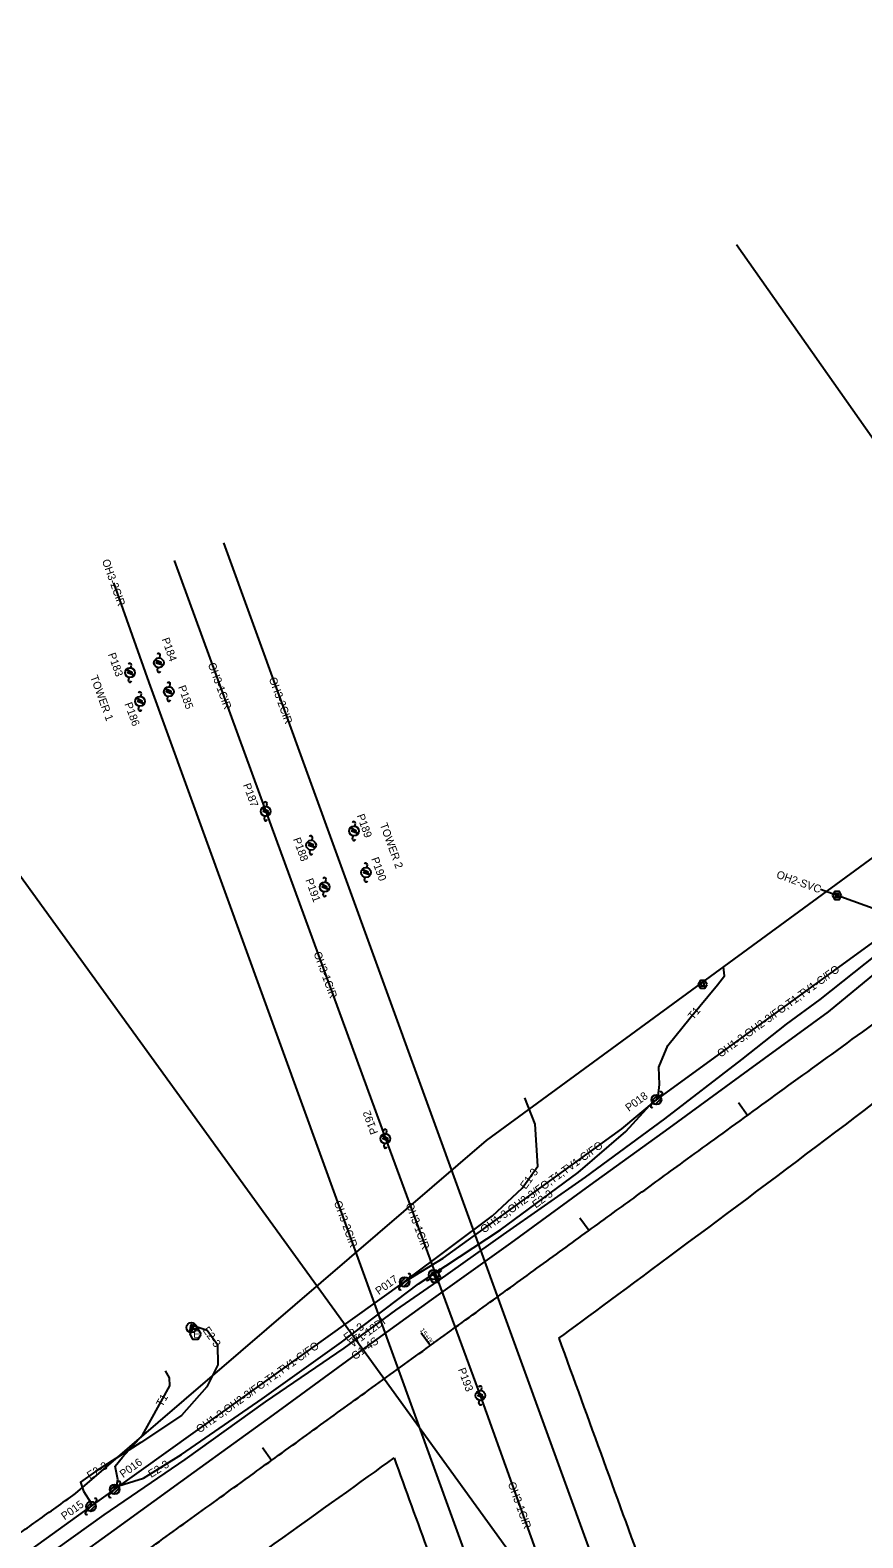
# Model space of a CAD drawing. Extents: x 1991878 to 2008544, y 770238 to 1141211.
# Drawn here: x 2004125 to 2004550, y 1139018 to 1139787 of the extents above; entities that cross this region are included whole.
import ezdxf

# ---------------------------------------------------------------- set-up
doc = ezdxf.new("R2010")
doc.units = 0
for name, color, linetype in [('RD_EX_SU_Elec', 7, 'Continuous'), ('RD_EX_SU_Gas', 7, 'Continuous'), ('RD_EX_SU_H2O', 7, 'Continuous'), ('RD_EX_SU_Ovhd', 7, 'Continuous'), ('RD_EX_SU_Pole', 7, 'Continuous'), ('RD_EX_SU_Sewer', 7, 'Continuous'), ('RD_EX_SU_SwpLmt', 7, 'Continuous'), ('RD_EX_SU_Telecom', 7, 'Continuous'), ('RD_EX_SU_TX_Elec', 7, 'Continuous'), ('RD_EX_SU_TX_Gas', 7, 'Continuous'), ('RD_EX_SU_TX_H2O', 7, 'Continuous'), ('RD_EX_SU_TX_Ovhd', 7, 'Continuous'), ('RD_EX_SU_TX_Pole', 7, 'Continuous'), ('RD_EX_SU_TX_Telecom', 7, 'Continuous'), ('RD_HC_Cl', 7, 'Continuous')]:
    doc.layers.add(name, color=color, linetype=linetype)

msp = doc.modelspace()

# ---------------------------------------------------------------- linework, layer by layer
at = {"layer": 'RD_EX_SU_Elec'}
for points in [[(2004168.09, 1139042.52), (2004168.01, 1139043.57), (2004182.88, 1139048.25), (2004202.25, 1139060.36), (2004243.35, 1139088.77), (2004283.94, 1139117.69), (2004323.11, 1139147.44), (2004365.07, 1139174.96), (2004404.63, 1139204.33), (2004429.06, 1139225.25), (2004443.17, 1139240.65), (2004444.61, 1139241.4)], [(2004316.12, 1139148.39), (2004317.11, 1139149.38), (2004360.95, 1139182.08), (2004376.07, 1139196.27), (2004384.08, 1139207.41), (2004382.8, 1139228.99), (2004377.45, 1139242.32)], [(2004208.14, 1139126.24), (2004215.41, 1139123.84), (2004220.67, 1139116.52), (2004220.86, 1139106.12), (2004215.25, 1139094.87), (2004202.23, 1139080.19), (2004181.54, 1139066.49), (2004158.37, 1139051.7), (2004150.66, 1139046.27), (2004152.27, 1139041.61), (2004156.08, 1139035.53), (2004156.05, 1139033.8)]]:
    msp.add_lwpolyline(points, dxfattribs=at)
for points in [[(2004208.71, 1139127.16), (2004207.7, 1139123.71), (2004207.2, 1139125.58), (2004206.44, 1139122.75), (2004207.13, 1139126.66), (2004207.69, 1139124.72)], [(2004212.25, 1139121.75), (2004210.81, 1139124.25), (2004207.92, 1139124.25), (2004206.48, 1139121.75), (2004207.92, 1139119.25), (2004210.81, 1139119.25)]]:
    msp.add_lwpolyline(points, close=True, dxfattribs=at)
msp.add_circle((2004207.32, 1139125.1), 2.55, dxfattribs=at)
at = {"layer": 'RD_EX_SU_Gas'}
msp.add_lwpolyline([(2004127.39, 1138992.43), (2004167.83, 1139021.75), (2004208.7, 1139051.33), (2004249.23, 1139080.61), (2004289.2, 1139109.77), (2004329.8, 1139139.24), (2004370.29, 1139168.18), (2004410.8, 1139197.77), (2004451.13, 1139226.8), (2004491.65, 1139256.41), (2004532.34, 1139286.17), (2004559.51, 1139308.55), (2004570.45, 1139319.96), (2004589.25, 1139345.84), (2004598.18, 1139366.3), (2004605.75, 1139385.94), (2004607.89, 1139395.38), (2004612.64, 1139396.79), (2004640.85, 1139410.39), (2004653.01, 1139417.54), (2004650.63, 1139421.79), (2004642.64, 1139434.89), (2004626.13, 1139463.52)], dxfattribs=at)
at = {"layer": 'RD_EX_SU_H2O'}
for p, q in [((2004334.21, 1139155.06), (2004332.65, 1139153.95)), ((2004334.94, 1139154.04), (2004334.21, 1139155.06)), ((2004328.65, 1139151.09), (2004327.03, 1139149.93)), ((2004327.03, 1139149.93), (2004327.77, 1139148.91)), ((2004327.77, 1139148.91), (2004329.42, 1139150.09)), ((2004331.81, 1139149.71), (2004332.76, 1139148.38)), ((2004332.76, 1139148.38), (2004333.79, 1139149.11)), ((2004333.79, 1139149.11), (2004332.86, 1139150.42)), ((2004333.35, 1139152.9), (2004334.94, 1139154.04))]:
    msp.add_line(p, q, dxfattribs=at)
for points in [[(2004122.45, 1139000.61), (2004162.73, 1139029.52), (2004204.05, 1139057.78), (2004245.07, 1139087.18), (2004285.23, 1139114.51), (2004311.58, 1139134.01), (2004333.1, 1139148.87), (2004366.63, 1139172.54), (2004408.38, 1139201.91), (2004448.87, 1139231.66), (2004488.17, 1139261.92), (2004511.05, 1139279.96), (2004528.13, 1139292.48), (2004557.12, 1139315.44), (2004575.83, 1139329.69), (2004595.34, 1139346.68), (2004617.3, 1139361.37), (2004649.17, 1139383.17), (2004663.69, 1139393.7), (2004675.95, 1139402.09), (2004682.78, 1139406.85), (2004687.52, 1139410.39), (2004690.03, 1139412.66)], [(2004330.96, 1139152.08), (2004331.38, 1139151.22), (2004332.8, 1139149.35), (2004333.12, 1139148.89)]]:
    msp.add_lwpolyline(points, dxfattribs=at)
msp.add_lwpolyline([(2004334.63, 1139150.7), (2004333.19, 1139153.2), (2004330.3, 1139153.2), (2004328.86, 1139150.7), (2004330.3, 1139148.2), (2004333.19, 1139148.2)], close=True, dxfattribs=at)
for radius in [2.52, 0.315]:
    msp.add_circle((2004330.96, 1139152.08), radius, dxfattribs=at)
for start, end in [(203.23728, 232.2136), (289.79782, 318.76505), (18.89099, 47.86731)]:
    msp.add_arc((2004330.96, 1139152.08), 2.52, start, end, dxfattribs=at)
at = {"layer": 'RD_EX_SU_Ovhd'}
for p, q in [((2004223.65, 1139525.67), (2004282.2, 1139364.47)), ((2004198.44, 1139516.51), (2004245.22, 1139388.55)), ((2004185.77, 1139454.37), (2004167.69, 1139505.27)), ((2004386.44, 1138901.38), (2004185.77, 1139454.37)), ((2004245.22, 1139388.55), (2004306.3, 1139221.53)), ((2004282.2, 1139364.47), (2004545.93, 1138638.38)), ((2004528.25, 1139348.79), (2004571.07, 1139333.35)), ((2004444.61, 1139241.4), (2004571.07, 1139333.35)), ((2004306.3, 1139221.53), (2004354.72, 1139090.45)), ((2004168.09, 1139042.52), (2004316.12, 1139148.39)), ((2004354.72, 1139090.45), (2004394.96, 1138978.21)), ((2004156.05, 1139033.8), (2004168.09, 1139042.52)), ((2004026.75, 1138941.13), (2004156.05, 1139033.8))]:
    msp.add_line(p, q, dxfattribs=at)
msp.add_lwpolyline([(2004316.12, 1139148.39), (2004335.77, 1139160.46), (2004427, 1139226.5), (2004444.61, 1139241.4)], dxfattribs=at)
at = {"layer": 'RD_EX_SU_Pole'}
for p, q in [((2004176.4, 1139461.77), (2004176.67, 1139463.25)), ((2004191.13, 1139466.83), (2004191.4, 1139468.3)), ((2004175.24, 1139455.38), (2004175.51, 1139456.85)), ((2004189.97, 1139460.43), (2004190.24, 1139461.91)), ((2004181.49, 1139447.13), (2004181.76, 1139448.61)), ((2004196.23, 1139452.09), (2004196.5, 1139453.57)), ((2004180.33, 1139440.73), (2004180.6, 1139442.21)), ((2004195.07, 1139445.7), (2004195.34, 1139447.17)), ((2004244.51, 1139384.62), (2004244.78, 1139386.09)), ((2004245.67, 1139391.01), (2004245.94, 1139392.49)), ((2004290.69, 1139380.96), (2004290.96, 1139382.43)), ((2004268.84, 1139373.77), (2004269.11, 1139375.25)), ((2004289.53, 1139374.56), (2004289.8, 1139376.04)), ((2004267.68, 1139367.38), (2004267.95, 1139368.85)), ((2004296.83, 1139359.81), (2004297.09, 1139361.28)), ((2004274.55, 1139346.03), (2004274.82, 1139347.51)), ((2004275.71, 1139352.43), (2004275.98, 1139353.91)), ((2004295.66, 1139353.41), (2004295.93, 1139354.89)), ((2004442.19, 1139240.76), (2004445.25, 1139243.82)), ((2004442.84, 1139239.64), (2004446.37, 1139243.17)), ((2004443.96, 1139238.99), (2004447.02, 1139242.05)), ((2004446.37, 1139243.17), (2004447.43, 1139244.23)), ((2004441.78, 1139238.58), (2004442.84, 1139239.64)), ((2004306.74, 1139223.99), (2004307.01, 1139225.46)), ((2004305.58, 1139217.59), (2004305.85, 1139219.07)), ((2004313.7, 1139147.74), (2004316.76, 1139150.8)), ((2004314.35, 1139146.62), (2004317.88, 1139150.15)), ((2004315.47, 1139145.97), (2004318.53, 1139149.03)), ((2004317.88, 1139150.15), (2004318.94, 1139151.21)), ((2004313.29, 1139145.56), (2004314.35, 1139146.62)), ((2004355.16, 1139092.91), (2004355.43, 1139094.39)), ((2004354, 1139086.52), (2004354.27, 1139087.99)), ((2004165.27, 1139039.69), (2004166.33, 1139040.75)), ((2004165.68, 1139041.87), (2004168.74, 1139044.93)), ((2004166.33, 1139040.75), (2004169.86, 1139044.29)), ((2004167.45, 1139040.1), (2004170.51, 1139043.17)), ((2004169.86, 1139044.29), (2004170.92, 1139045.35)), ((2004153.22, 1139030.97), (2004154.28, 1139032.03)), ((2004153.63, 1139033.15), (2004156.69, 1139036.21)), ((2004154.28, 1139032.03), (2004157.81, 1139035.57)), ((2004155.4, 1139031.38), (2004158.46, 1139034.44)), ((2004157.81, 1139035.57), (2004158.87, 1139036.63))]:
    msp.add_line(p, q, dxfattribs=at)
for points in [[(2004189.22, 1139465.79), (2004191.04, 1139464.61), (2004189.39, 1139464.44), (2004192.46, 1139463.3), (2004192.46, 1139463.3), (2004190.28, 1139464.34), (2004191.87, 1139464.47)], [(2004174.49, 1139460.74), (2004176.31, 1139459.55), (2004174.66, 1139459.39), (2004177.73, 1139458.25), (2004177.73, 1139458.25), (2004175.55, 1139459.29), (2004177.14, 1139459.41)], [(2004194.32, 1139451.06), (2004196.14, 1139449.88), (2004194.49, 1139449.71), (2004197.56, 1139448.57), (2004197.56, 1139448.57), (2004195.38, 1139449.61), (2004196.97, 1139449.74)], [(2004179.58, 1139446.1), (2004181.4, 1139444.91), (2004179.75, 1139444.74), (2004182.82, 1139443.6), (2004182.82, 1139443.6), (2004180.64, 1139444.64), (2004182.23, 1139444.77)], [(2004243.76, 1139389.98), (2004245.58, 1139388.79), (2004243.93, 1139388.63), (2004247, 1139387.49), (2004247, 1139387.49), (2004244.82, 1139388.53), (2004246.41, 1139388.66)], [(2004288.78, 1139379.92), (2004290.6, 1139378.74), (2004288.95, 1139378.57), (2004292.02, 1139377.43), (2004292.02, 1139377.43), (2004289.84, 1139378.47), (2004291.43, 1139378.6)], [(2004266.93, 1139372.74), (2004268.75, 1139371.55), (2004267.1, 1139371.38), (2004270.17, 1139370.24), (2004270.17, 1139370.24), (2004267.99, 1139371.29), (2004269.58, 1139371.41)], [(2004294.91, 1139358.78), (2004296.74, 1139357.59), (2004295.08, 1139357.42), (2004298.15, 1139356.28), (2004298.15, 1139356.28), (2004295.97, 1139357.32), (2004297.56, 1139357.45)], [(2004273.8, 1139351.4), (2004275.62, 1139350.21), (2004273.97, 1139350.04), (2004277.04, 1139348.9), (2004277.04, 1139348.9), (2004274.86, 1139349.94), (2004276.45, 1139350.07)], [(2004304.83, 1139222.95), (2004306.65, 1139221.77), (2004305, 1139221.6), (2004308.07, 1139220.46), (2004308.07, 1139220.46), (2004305.89, 1139221.5), (2004307.48, 1139221.63)], [(2004353.25, 1139091.88), (2004355.07, 1139090.69), (2004353.42, 1139090.52), (2004356.49, 1139089.38), (2004356.49, 1139089.38), (2004354.31, 1139090.43), (2004355.9, 1139090.55)]]:
    msp.add_lwpolyline(points, close=True, dxfattribs=at)
for centre in [(2004190.69, 1139464.37), (2004175.95, 1139459.31), (2004195.79, 1139449.63), (2004181.04, 1139444.67), (2004245.22, 1139388.55), (2004290.25, 1139378.5), (2004268.4, 1139371.31), (2004296.38, 1139357.35), (2004275.27, 1139349.97), (2004444.61, 1139241.4), (2004306.3, 1139221.53), (2004316.12, 1139148.39), (2004354.72, 1139090.45), (2004168.09, 1139042.52), (2004156.05, 1139033.8)]:
    msp.add_circle(centre, 2.5, dxfattribs=at)
for centre, start, end in [((2004175.93, 1139463.38), 349.68899, 169.68899), ((2004190.66, 1139468.44), 349.68899, 169.68899), ((2004175.98, 1139455.24), 169.68899, 349.68899), ((2004190.71, 1139460.3), 169.68899, 349.68899), ((2004181.02, 1139448.74), 349.68899, 169.68899), ((2004195.76, 1139453.7), 349.68899, 169.68899), ((2004181.07, 1139440.6), 169.68899, 349.68899), ((2004195.81, 1139445.56), 169.68899, 349.68899), ((2004245.2, 1139392.62), 349.68899, 169.68899), ((2004245.25, 1139384.48), 169.68899, 349.68899), ((2004290.22, 1139382.57), 349.68899, 169.68899), ((2004268.37, 1139375.38), 349.68899, 169.68899), ((2004290.27, 1139374.43), 169.68899, 349.68899), ((2004268.42, 1139367.24), 169.68899, 349.68899), ((2004296.36, 1139361.42), 349.68899, 169.68899), ((2004275.24, 1139354.04), 349.68899, 169.68899), ((2004296.4, 1139353.28), 169.68899, 349.68899), ((2004275.29, 1139345.9), 169.68899, 349.68899), ((2004446.9, 1139244.76), 315.01158, 135.01158), ((2004442.31, 1139238.04), 135.01158, 315.01158), ((2004306.27, 1139225.6), 349.68899, 169.68899), ((2004306.32, 1139217.46), 169.68899, 349.68899), ((2004318.41, 1139151.75), 315.01158, 135.01158), ((2004313.82, 1139145.03), 135.01158, 315.01158), ((2004354.69, 1139094.52), 349.68899, 169.68899), ((2004354.74, 1139086.38), 169.68899, 349.68899), ((2004165.8, 1139039.16), 135.01158, 315.01158), ((2004170.39, 1139045.88), 315.01158, 135.01158), ((2004158.34, 1139037.16), 315.01158, 135.01158), ((2004153.75, 1139030.44), 135.01158, 315.01158)]:
    msp.add_arc(centre, 0.75, start, end, dxfattribs=at)
at = {"layer": 'RD_EX_SU_Sewer'}
for points in [[(2004539.11, 1139345.64), (2004537.96, 1139347.64), (2004535.65, 1139347.64), (2004534.5, 1139345.64), (2004535.65, 1139343.64), (2004537.96, 1139343.64)], [(2004537.62, 1139346.45), (2004535.99, 1139346.46), (2004535.99, 1139344.82), (2004537.62, 1139344.82)], [(2004470.49, 1139300.25), (2004469.34, 1139302.25), (2004467.03, 1139302.25), (2004465.88, 1139300.25), (2004467.03, 1139298.26), (2004469.34, 1139298.26)], [(2004469, 1139301.07), (2004467.37, 1139301.07), (2004467.37, 1139299.44), (2004469, 1139299.44)]]:
    msp.add_lwpolyline(points, close=True, dxfattribs=at)
at = {"layer": 'RD_EX_SU_SwpLmt'}
for p, q in [((2004357.93, 1139220.65), (2004592.56, 1139392.56)), ((2004148.08, 1139040.37), (2004357.93, 1139220.65))]:
    msp.add_line(p, q, dxfattribs=at)
for points, degree in [([(2004394.78, 1139119.65), (2004422.38, 1139139.88), (2004545.39, 1139230.86), (2004674.47, 1139331.94), (2004798.6, 1139426.11), (2004803.15, 1139429.56)], 3), ([(2003904.13, 1138805.76), (2003963.45, 1138830.79), (2004071.64, 1138887.18), (2004169.39, 1138957.24), (2004278.15, 1139035.08), (2004310.69, 1139058.54)], 3), ([(2004019.84, 1138953.87), (2004060.69, 1138978.54), (2004097.42, 1139004.2), (2004148.08, 1139040.37)], 2)]:
    msp.add_open_spline(points, degree=degree, dxfattribs=at)
for points in [[(2004394.78, 1139119.65), (2004440.28, 1138994.6), (2004535.99, 1138728.08), (2004687.71, 1138314.66), (2004781.55, 1138057.24), (2005017.8, 1137400.02), (2005029.38, 1137367.89)], [(2004310.69, 1139058.54), (2004346.25, 1138960.58), (2004422.68, 1138747.32)]]:
    msp.add_spline(points, degree=3, dxfattribs=at)
at = {"layer": 'RD_EX_SU_Telecom'}
for points in [[(2004444.61, 1139241.4), (2004445.56, 1139243.12), (2004446.11, 1139249.15), (2004445.81, 1139257.93), (2004450.46, 1139269.14), (2004461.75, 1139283.13), (2004475.72, 1139300.02), (2004479.4, 1139304.58), (2004478.75, 1139309.17)], [(2004168.09, 1139042.52), (2004169.08, 1139043.58), (2004169.77, 1139047.51), (2004168.39, 1139054.32), (2004172.18, 1139058.88), (2004182.28, 1139070.13), (2004186.65, 1139077.81), (2004196.27, 1139095.44), (2004196.18, 1139099.49), (2004194.14, 1139102.96)]]:
    msp.add_lwpolyline(points, dxfattribs=at)
at = {"layer": 'RD_HC_Cl'}
for p, q in [((2004485.41, 1139677.79), (2004904.59, 1139081.9)), ((2004092.14, 1139394.06), (2004519.36, 1138803.91)), ((2004486.44, 1139239.92), (2004491.14, 1139233.44)), ((2004405.51, 1139181.17), (2004410.21, 1139174.7)), ((2004324.56, 1139122.48), (2004329.25, 1139116)), ((2004243.55, 1139063.86), (2004248.24, 1139057.38))]:
    msp.add_line(p, q, dxfattribs=at)
msp.add_open_spline([(2002937.27, 1138556.06), (2003081.12, 1138596.24), (2003224.54, 1138636.27), (2003324.8, 1138664.72), (2003440.8, 1138697.76), (2003610.3, 1138743.13), (2003753.45, 1138782.34), (2003851.96, 1138815.09), (2003945.32, 1138855.48), (2004023.07, 1138899.74), (2004117.46, 1138962.96), (2004239.69, 1139051.13), (2004401.3, 1139168.16), (2004522.74, 1139256.47), (2004724.1, 1139402.13), (2005003.72, 1139590.96), (2005189.76, 1139724.82), (2005285.27, 1139787.25)], degree=2, dxfattribs=at)

# ---------------------------------------------------------------- texts
at = {"layer": 'RD_EX_SU_Elec'}
msp.add_text('E', height=3.75, dxfattribs=at).set_placement((2004208.23, 1139119.88))
at = {"layer": 'RD_EX_SU_H2O'}
msp.add_text('V', height=3.75, dxfattribs=at).set_placement((2004330.54, 1139148.82))
at = {"layer": 'RD_EX_SU_TX_Elec'}
for s, rotation, p in [('E1-3', 54.2641, (2004377.9, 1139195.38)), ('E2-3', 36.59248, (2004383.06, 1139185.83)), ('E2-3', 305.67934, (2004212.81, 1139123.81)), ('E2-3', 37.21272, (2004286.82, 1139117.88)), ('E2-3', 32.56985, (2004155.54, 1139047.49)), ('E2-3', 32.01859, (2004186.76, 1139048.29))]:
    msp.add_text(s, height=4, rotation=rotation, dxfattribs=at).set_placement(p)
at = {"layer": 'RD_EX_SU_TX_Gas'}
msp.add_text('G1-4S', height=4, rotation=35.97095, dxfattribs=at).set_placement((2004290.7, 1139108.36))
at = {"layer": 'RD_EX_SU_TX_H2O'}
msp.add_text('W1-12DI', height=4, rotation=36.50074, dxfattribs=at).set_placement((2004289.77, 1139114.83))
at = {"layer": 'RD_EX_SU_TX_Ovhd'}
for s, rotation, p in [('OH3-2CIR', 289.55471, (2004161.59, 1139516.45)), ('OH3-1CIR', 290.08462, (2004215.63, 1139463.66)), ('OH3-2CIR', 289.96176, (2004246.75, 1139456.21)), ('OH2-SVC', 340.17659, (2004505.47, 1139354.78)), ('OH3-1CIR', 290.08462, (2004269.56, 1139316.17)), ('OH1-3,OH2-3/FO,T1,TV1-C/FO', 36.02096, (2004477.4, 1139262.77)), ('OH1-3,OH2-3/FO,T1,TV1-C/FO', 35.90198, (2004356.54, 1139173.02)), ('OH3-2CIR', 289.94504, (2004279.93, 1139189.02)), ('OH3-1CIR', 290.27443, (2004316.56, 1139187.97)), ('OH1-3,OH2-3/FO,T1,TV1-C/FO', 35.57285, (2004211.47, 1139071.08)), ('OH3-1CIR', 289.72403, (2004368.71, 1139045.5))]:
    msp.add_text(s, height=4, rotation=rotation, dxfattribs=at).set_placement(p)
at = {"layer": 'RD_EX_SU_TX_Pole'}
for s, rotation, p in [('P184', 289.55471, (2004192.09, 1139476.42)), ('P183', 289.55471, (2004164.66, 1139468.7)), ('TOWER 1', 289.94504, (2004155.6, 1139457.19)), ('P185', 289.94504, (2004200.42, 1139452.06)), ('P186', 289.94504, (2004173.08, 1139443.39)), ('P187', 290.08462, (2004233.57, 1139402.07)), ('P189', 289.96176, (2004291.61, 1139386.41)), ('TOWER 2', 289.96176, (2004303.38, 1139381.83)), ('P188', 289.96176, (2004259.08, 1139374.38)), ('P190', 289.96176, (2004298.96, 1139364.34)), ('P191', 289.96176, (2004265.41, 1139353.54)), ('P018', 36.02096, (2004430.53, 1139235.16)), ('P192', 110.08462, (2004302.63, 1139224.52)), ('P017', 35.57285, (2004302.94, 1139141.62)), ('P193', 290.27443, (2004343.23, 1139103.73)), ('P016', 35.57285, (2004172.46, 1139048.25)), ('P015', 35.62946, (2004142.6, 1139026.71))]:
    msp.add_text(s, height=4, rotation=rotation, dxfattribs=at).set_placement(p)
at = {"layer": 'RD_EX_SU_TX_Telecom'}
for rotation, p in [(50.39377, (2004463.34, 1139281.88)), (61.36995, (2004192.51, 1139084.33))]:
    msp.add_text('T1', height=4, rotation=rotation, dxfattribs=at).set_placement(p)
at = {"layer": 'RD_HC_Cl'}
msp.add_text('15+00', height=2.5, rotation=305.91604, dxfattribs=at).set_placement((2004323.64, 1139123.75))

doc.saveas('drawing.dxf')
